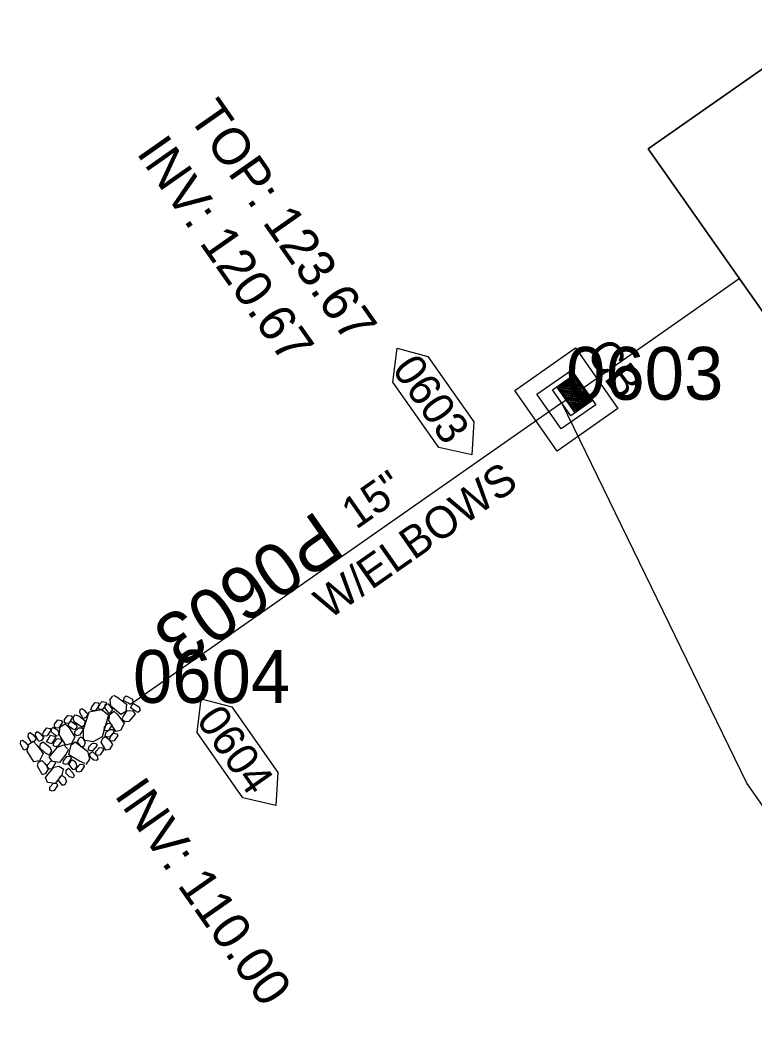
# Model space of a CAD drawing. Extents: x 2296558 to 2299313, y 599200 to 601383.
# Drawn here: x 2297890.7 to 2297960.1, y 600322.8 to 600419.2 of the extents above; entities that cross this region are included whole.
import ezdxf

# ---------------------------------------------------------------- set-up
doc = ezdxf.new("R2010")
doc.units = 0
for name, color, linetype in [('Prop Drainage Structure Box Number Symbol CELL', 7, 'Continuous'), ('Prop Drainage Structure Catch Basin Grate 840 03G CELL', 7, 'Continuous'), ('Prop Drainage Structure Catch Basin Grate 840 03G Label', 7, 'Continuous'), ('Prop Drainage Structure Pipe Alternate 15in', 7, 'Continuous'), ('Prop Drainage Structure Pipe Alternate 15in Label', 7, 'Continuous'), ('Prop Drainage Structure Plot Symbol 20 Scale', 7, 'Continuous'), ('Prop Drainage Structure Plot Symbol 50 Scale', 7, 'Continuous'), ('Prop Drainage Structure Tops and Inverts LABEL', 7, 'Continuous'), ('Prop Erosion Rip Rap Pad at Outlet CELL', 7, 'Continuous'), ('Prop Plan Preparation Watershed Post Construction', 7, 'Continuous'), ('Scratch_Level_3', 7, 'Continuous'), ('Scratch_Level_5', 7, 'Continuous')]:
    doc.layers.add(name, color=color, linetype=linetype)

msp = doc.modelspace()

# ---------------------------------------------------------------- linework, layer by layer
at = {"layer": 'Prop Drainage Structure Box Number Symbol CELL'}
for points in [[(2297929.189, 600387.346), (2297933.527, 600381.151), (2297933.35, 600378.022), (2297930.234, 600378.729), (2297925.895, 600384.924), (2297926.278, 600388.121), (2297929.189, 600387.346)], [(2297910.665, 600354.186), (2297915.004, 600347.992), (2297914.828, 600344.863), (2297911.711, 600345.569), (2297907.372, 600351.763), (2297907.754, 600354.96), (2297910.665, 600354.186)]]:
    msp.add_lwpolyline(points, dxfattribs=at)
at = {"layer": 'Prop Drainage Structure Catch Basin Grate 840 03G CELL'}
for p, q in [((2297942.139, 600384.807), (2297943.62, 600384.527)), ((2297942.231, 600385.046), (2297942.231, 600385.046)), ((2297943.434, 600384.636), (2297942.342, 600384.843)), ((2297942.365, 600384.966), (2297943.458, 600384.759)), ((2297943.272, 600384.868), (2297942.568, 600385.001)), ((2297942.591, 600385.124), (2297943.295, 600384.991)), ((2297943.109, 600385.1), (2297942.795, 600385.16)), ((2297942.818, 600385.283), (2297943.132, 600385.223)), ((2297943.597, 600384.404), (2297942.115, 600384.684)), ((2297943.114, 600383.847), (2297943.114, 600383.847)), ((2297943.392, 600383.966), (2297944.108, 600383.83)), ((2297943.618, 600384.124), (2297943.945, 600384.062)), ((2297943.89, 600384.391), (2297943.89, 600384.391)), ((2297941.851, 600382.963), (2297941.851, 600382.963)), ((2297942.502, 600383.328), (2297944.127, 600383.021)), ((2297942.664, 600383.096), (2297943.9, 600382.862)), ((2297942.713, 600383.49), (2297944.353, 600383.179)), ((2297942.939, 600383.648), (2297944.433, 600383.365)), ((2297943.165, 600383.807), (2297944.271, 600383.598)), ((2297942.827, 600382.864), (2297943.674, 600382.704)), ((2297942.989, 600382.632), (2297943.448, 600382.545)), ((2297943.198, 600382.264), (2297943.129, 600382.277)), ((2297943.152, 600382.4), (2297943.221, 600382.386)), ((2297943.974, 600382.618), (2297943.974, 600382.618))]:
    msp.add_line(p, q, dxfattribs=at)
for points in [[(2297943.121, 600382.021), (2297941.4, 600384.478), (2297943.038, 600385.625), (2297944.759, 600383.168), (2297942.711, 600381.734), (2297940.99, 600384.191), (2297941.4, 600384.478)], [(2297943.123, 600382.035), (2297941.414, 600384.476), (2297943.036, 600385.611), (2297944.745, 600383.171), (2297943.123, 600382.035)], [(2297943.005, 600385.437), (2297944.57, 600383.201), (2297943.154, 600382.209), (2297941.588, 600384.445), (2297943.005, 600385.437)], [(2297941.686, 600384.49), (2297943.447, 600384.157), (2297943.304, 600384.056), (2297941.663, 600384.367)], [(2297941.851, 600384.257), (2297943.22, 600383.998), (2297943.077, 600383.898), (2297941.828, 600384.134)], [(2297941.912, 600384.649), (2297943.673, 600384.315), (2297943.53, 600384.215), (2297941.889, 600384.526)], [(2297942.014, 600384.025), (2297942.994, 600383.839), (2297942.851, 600383.739), (2297941.991, 600383.902)], [(2297944.085, 600383.707), (2297943.249, 600383.865), (2297943.392, 600383.966)], [(2297943.922, 600383.939), (2297943.475, 600384.024), (2297943.618, 600384.124)], [(2297942.176, 600383.793), (2297942.768, 600383.681), (2297942.625, 600383.581), (2297942.153, 600383.67)], [(2297942.339, 600383.561), (2297942.541, 600383.522), (2297942.398, 600383.422), (2297942.316, 600383.438)], [(2297944.104, 600382.898), (2297942.478, 600383.206), (2297942.502, 600383.328)], [(2297944.33, 600383.056), (2297942.57, 600383.39), (2297942.713, 600383.49)], [(2297943.877, 600382.739), (2297942.641, 600382.973), (2297942.664, 600383.096)], [(2297944.41, 600383.243), (2297942.796, 600383.548), (2297942.939, 600383.648)], [(2297944.247, 600383.475), (2297943.022, 600383.707), (2297943.165, 600383.807)], [(2297943.651, 600382.581), (2297942.804, 600382.741), (2297942.827, 600382.864)], [(2297943.424, 600382.422), (2297942.966, 600382.509), (2297942.989, 600382.632)]]:
    msp.add_lwpolyline(points, dxfattribs=at)
for centre, start, end in [((2297942.127, 600384.746), 79.2754, 259.2754), ((2297942.353, 600384.904), 79.2754, 259.2754), ((2297942.58, 600385.063), 79.2754, 259.2754), ((2297942.806, 600385.221), 79.2754, 259.2754), ((2297943.121, 600385.162), 259.2754, 79.2754), ((2297943.283, 600384.93), 259.2754, 79.2754), ((2297941.674, 600384.429), 79.2754, 259.2754), ((2297941.84, 600384.196), 79.2754, 259.2754), ((2297941.901, 600384.587), 79.2754, 259.2754), ((2297942.002, 600383.964), 79.2754, 259.2754), ((2297943.446, 600384.697), 259.2754, 79.2754), ((2297943.609, 600384.465), 259.2754, 79.2754), ((2297943.934, 600384.001), 259.2754, 79.2754), ((2297942.165, 600383.731), 79.2754, 259.2754), ((2297942.327, 600383.499), 79.2754, 259.2754), ((2297944.096, 600383.768), 259.2754, 79.2754), ((2297944.115, 600382.959), 259.2754, 79.2754), ((2297944.259, 600383.536), 259.2754, 79.2754), ((2297944.342, 600383.118), 259.2754, 79.2754), ((2297944.422, 600383.304), 259.2754, 79.2754), ((2297943.14, 600382.338), 79.2754, 259.2754), ((2297943.21, 600382.325), 259.2754, 79.2754), ((2297943.436, 600382.484), 259.2754, 79.2754), ((2297943.662, 600382.642), 259.2754, 79.2754), ((2297943.889, 600382.801), 259.2754, 79.2754)]:
    msp.add_arc(centre, 0.0625, start, end, dxfattribs=at)
at = {"layer": 'Prop Drainage Structure Pipe Alternate 15in'}
msp.add_line((2297941.851, 600382.963), (2297901.304, 600354.569), dxfattribs=at)
at = {"layer": 'Prop Drainage Structure Plot Symbol 20 Scale'}
msp.add_lwpolyline([(2297942.785, 600386.059), (2297945.08, 600382.782), (2297941.803, 600380.488), (2297939.509, 600383.764)], close=True, dxfattribs=at)
at = {"layer": 'Prop Drainage Structure Plot Symbol 50 Scale'}
msp.add_lwpolyline([(2297943.154, 600388.148), (2297947.169, 600382.414), (2297941.435, 600378.399), (2297937.42, 600384.133)], close=True, dxfattribs=at)
at = {"layer": 'Prop Erosion Rip Rap Pad at Outlet CELL'}
msp.add_line((2297901.304, 600354.569), (2297901.304, 600354.569), dxfattribs=at)
msp.add_line((2297901.304, 600354.569), (2297901.304, 600354.569), dxfattribs=at)
for points in [[(2297899.5, 600355.292), (2297899.883, 600355.072), (2297900.709, 600354.459), (2297900.628, 600353.747), (2297900.166, 600353.469), (2297899.229, 600354.263), (2297899.135, 600354.898), (2297899.398, 600355.22)], [(2297901.057, 600354.398), (2297900.874, 600354.529), (2297900.399, 600354.792), (2297900.52, 600355.121), (2297900.674, 600355.228), (2297901.254, 600354.902), (2297901.303, 600354.57), (2297901.057, 600354.398)], [(2297896.488, 600354.037), (2297896.732, 600353.841), (2297897.052, 600353.471), (2297896.84, 600353.185), (2297896.589, 600353.085), (2297896.275, 600353.643), (2297896.32, 600353.95), (2297896.488, 600354.037)], [(2297897.337, 600353.914), (2297897.406, 600354.207), (2297897.734, 600354.589), (2297898.026, 600354.564), (2297898.155, 600354.38), (2297897.758, 600353.858), (2297897.536, 600353.825), (2297897.337, 600353.914)], [(2297898.048, 600354.031), (2297898.063, 600354.316), (2297898.39, 600354.698), (2297898.704, 600354.642), (2297898.811, 600354.489), (2297898.459, 600353.967), (2297898.217, 600353.92), (2297898.048, 600354.031)], [(2297898.964, 600354.489), (2297899.103, 600354.312), (2297899.372, 600353.95), (2297899.197, 600353.676), (2297899.044, 600353.568), (2297898.689, 600354.053), (2297898.691, 600354.42), (2297898.964, 600354.489)], [(2297901.761, 600353.655), (2297901.56, 600353.789), (2297901.064, 600354.083), (2297901.224, 600354.378), (2297901.37, 600354.495), (2297901.898, 600354.178), (2297901.999, 600353.837), (2297901.761, 600353.655)], [(2297894.819, 600352.715), (2297894.833, 600353), (2297895.161, 600353.382), (2297895.474, 600353.327), (2297895.582, 600353.173), (2297895.237, 600352.642), (2297894.988, 600352.605), (2297894.819, 600352.715)], [(2297895.853, 600353.44), (2297896.202, 600353.333), (2297896.763, 600352.902), (2297896.711, 600352.454), (2297896.466, 600352.282), (2297895.733, 600352.761), (2297895.665, 600353.186), (2297895.853, 600353.44)], [(2297896.643, 600351.2), (2297896.623, 600352.056), (2297897.158, 600353.712), (2297898.345, 600353.934), (2297899.002, 600353.432), (2297898.394, 600351.358), (2297897.538, 600350.881), (2297896.605, 600351.036)], [(2297899.501, 600353.766), (2297899.883, 600353.438), (2297900.484, 600352.623), (2297900.139, 600351.939), (2297899.693, 600351.856), (2297899.025, 600352.898), (2297899.126, 600353.473), (2297899.501, 600353.766)], [(2297900.261, 600352.986), (2297900.399, 600353.311), (2297900.744, 600353.843), (2297901.285, 600353.81), (2297901.525, 600353.49), (2297900.91, 600352.8), (2297900.557, 600352.781), (2297900.261, 600352.986)], [(2297892.745, 600351.492), (2297892.846, 600351.807), (2297893.159, 600352.209), (2297893.442, 600352.132), (2297893.542, 600351.989), (2297893.194, 600351.44), (2297892.945, 600351.403), (2297892.745, 600351.492)], [(2297894.135, 600351.382), (2297893.952, 600351.513), (2297893.58, 600351.848), (2297893.625, 600352.154), (2297893.741, 600352.25), (2297894.215, 600351.987), (2297894.295, 600351.677), (2297894.206, 600351.477)], [(2297893.872, 600352.281), (2297893.886, 600352.566), (2297894.214, 600352.948), (2297894.527, 600352.893), (2297894.635, 600352.739), (2297894.29, 600352.207), (2297894.041, 600352.17), (2297893.872, 600352.281)], [(2297894.892, 600352.568), (2297895.285, 600352.202), (2297895.804, 600351.33), (2297895.492, 600350.73), (2297894.969, 600350.562), (2297894.342, 600351.588), (2297894.433, 600352.308), (2297894.892, 600352.568)], [(2297895.816, 600352.01), (2297895.602, 600352.12), (2297895.149, 600352.397), (2297895.3, 600352.747), (2297895.433, 600352.84), (2297895.972, 600352.485), (2297895.998, 600352.274), (2297895.816, 600352.01)], [(2297895.82, 600351.57), (2297895.824, 600351.847), (2297896.183, 600352.206), (2297896.468, 600352.191), (2297896.597, 600352.007), (2297896.237, 600351.496), (2297895.989, 600351.459), (2297895.82, 600351.57)], [(2297898.587, 600351.997), (2297898.602, 600352.282), (2297898.937, 600352.654), (2297899.246, 600352.626), (2297899.323, 600352.451), (2297898.984, 600351.954), (2297898.787, 600351.908), (2297898.587, 600351.997)], [(2297898.691, 600351.414), (2297898.746, 600351.727), (2297899.092, 600352.061), (2297899.387, 600352.054), (2297899.516, 600351.869), (2297899.109, 600351.34), (2297898.891, 600351.325), (2297898.691, 600351.414)], [(2297891.598, 600351.757), (2297891.842, 600351.562), (2297892.163, 600351.191), (2297891.951, 600350.905), (2297891.7, 600350.806), (2297891.386, 600351.364), (2297891.431, 600351.67), (2297891.598, 600351.757)], [(2297892.279, 600351.853), (2297892.533, 600351.664), (2297892.854, 600351.294), (2297892.642, 600351.008), (2297892.391, 600350.909), (2297892.077, 600351.467), (2297892.122, 600351.773), (2297892.279, 600351.853)], [(2297893.134, 600350.894), (2297893.244, 600351.063), (2297893.522, 600351.517), (2297893.888, 600351.408), (2297893.996, 600351.254), (2297893.61, 600350.694), (2297893.355, 600350.775), (2297893.134, 600350.894)], [(2297893.801, 600350.507), (2297893.839, 600350.824), (2297894.174, 600351.196), (2297894.487, 600351.14), (2297894.574, 600350.972), (2297894.228, 600350.486), (2297894.001, 600350.418), (2297893.801, 600350.507)], [(2297896.373, 600351.347), (2297896.647, 600351.173), (2297896.802, 600350.777), (2297896.64, 600350.42), (2297896.422, 600350.404), (2297896.068, 600350.889), (2297896.219, 600351.239), (2297896.373, 600351.347)], [(2297898.685, 600351.379), (2297899.017, 600351.123), (2297899.371, 600350.639), (2297899.088, 600350.15), (2297898.746, 600350.094), (2297898.312, 600350.843), (2297898.449, 600351.214), (2297898.685, 600351.379)], [(2297899.133, 600351.021), (2297899.141, 600351.316), (2297899.475, 600351.688), (2297899.792, 600351.65), (2297899.869, 600351.475), (2297899.523, 600350.989), (2297899.333, 600350.932), (2297899.133, 600351.021)], [(2297890.873, 600351.051), (2297891.116, 600350.855), (2297891.437, 600350.484), (2297891.225, 600350.199), (2297890.974, 600350.099), (2297890.66, 600350.657), (2297890.705, 600350.964), (2297890.873, 600351.051)], [(2297891.857, 600350.931), (2297892.222, 600350.561), (2297892.823, 600349.791), (2297892.457, 600349.093), (2297891.936, 600348.987), (2297891.288, 600349.999), (2297891.434, 600350.62), (2297891.857, 600350.931)], [(2297893.367, 600349.624), (2297893.02, 600349.792), (2297892.499, 600350.297), (2297892.572, 600350.715), (2297892.818, 600350.887), (2297893.479, 600350.358), (2297893.612, 600349.993), (2297893.367, 600349.624)], [(2297895.218, 600350.141), (2297894.998, 600349.758), (2297894.355, 600348.911), (2297893.683, 600349.02), (2297893.371, 600349.443), (2297894.179, 600350.36), (2297894.76, 600350.599), (2297895.122, 600350.212)], [(2297896.753, 600348.82), (2297896.262, 600349.041), (2297895.25, 600349.66), (2297895.45, 600350.594), (2297895.842, 600350.884), (2297897.021, 600349.985), (2297897.204, 600349.243), (2297896.835, 600348.725)], [(2297897.101, 600350.132), (2297897.14, 600350.404), (2297897.479, 600350.748), (2297897.781, 600350.73), (2297897.91, 600350.546), (2297897.519, 600350.059), (2297897.301, 600350.043), (2297897.101, 600350.132)], [(2297897.784, 600349.68), (2297897.809, 600349.972), (2297898.143, 600350.343), (2297898.442, 600350.309), (2297898.519, 600350.133), (2297898.191, 600349.644), (2297897.994, 600349.598), (2297897.784, 600349.68)], [(2297894.71, 600348.839), (2297894.736, 600349.086), (2297895.075, 600349.538), (2297895.389, 600349.483), (2297895.466, 600349.308), (2297895.121, 600348.776), (2297894.931, 600348.72), (2297894.71, 600348.839)], [(2297895.579, 600349.189), (2297895.854, 600349.015), (2297896.009, 600348.619), (2297895.847, 600348.262), (2297895.629, 600348.247), (2297895.274, 600348.731), (2297895.426, 600349.081), (2297895.579, 600349.189)], [(2297897.853, 600349.102), (2297897.592, 600349.148), (2297897.253, 600349.414), (2297897.234, 600349.768), (2297897.493, 600349.964), (2297897.909, 600349.523), (2297897.999, 600349.22), (2297897.853, 600349.102)], [(2297892.685, 600349.116), (2297892.955, 600348.862), (2297893.331, 600348.347), (2297893.023, 600347.871), (2297892.744, 600347.768), (2297892.278, 600348.586), (2297892.387, 600348.953), (2297892.685, 600349.116)], [(2297894.713, 600348.247), (2297894.565, 600347.761), (2297893.953, 600346.936), (2297893.24, 600347.016), (2297893.031, 600347.511), (2297893.81, 600348.469), (2297894.286, 600348.573), (2297894.775, 600348.29)], [(2297893.215, 600348.403), (2297893.24, 600348.695), (2297893.56, 600349.087), (2297893.873, 600349.032), (2297893.981, 600348.878), (2297893.626, 600348.339), (2297893.384, 600348.292), (2297893.215, 600348.403)], [(2297895.646, 600347.481), (2297895.311, 600347.567), (2297894.989, 600347.875), (2297894.974, 600348.2), (2297895.213, 600348.383), (2297895.629, 600347.942), (2297895.75, 600347.66), (2297895.646, 600347.481)], [(2297895.969, 600348.088), (2297895.976, 600348.383), (2297896.311, 600348.755), (2297896.62, 600348.727), (2297896.697, 600348.552), (2297896.368, 600348.062), (2297896.179, 600348.006), (2297895.969, 600348.088)], [(2297894.59, 600347.703), (2297894.855, 600347.522), (2297895.009, 600347.126), (2297894.84, 600346.779), (2297894.622, 600346.764), (2297894.268, 600347.248), (2297894.437, 600347.595), (2297894.59, 600347.703)], [(2297893.447, 600346.307), (2297893.454, 600346.602), (2297893.789, 600346.973), (2297894.105, 600346.936), (2297894.182, 600346.761), (2297893.853, 600346.271), (2297893.657, 600346.225), (2297893.447, 600346.307)]]:
    msp.add_lwpolyline(points, dxfattribs=at)
at = {"layer": 'Prop Plan Preparation Watershed Post Construction'}
for p, q in [((2297950.039, 600407.009), (2297967.377, 600419.15)), ((2298066.924, 600240.095), (2297950.039, 600407.009)), ((2297941.851, 600382.963), (2297958.643, 600394.722))]:
    msp.add_line(p, q, dxfattribs=at)
msp.add_lwpolyline([(2297958.643, 600394.722), (2298066.924, 600240.095), (2298044.979, 600224.727), (2297959.371, 600346.975), (2297941.851, 600382.963)], dxfattribs=at)
at = {"layer": 'Scratch_Level_5'}
for p, q in [((2297967.377, 600419.15), (2297950.039, 600407.009)), ((2297950.039, 600407.009), (2297952.496, 600408.729)), ((2297950.039, 600407.009), (2298066.924, 600240.095))]:
    msp.add_line(p, q, dxfattribs=at)

# ---------------------------------------------------------------- texts
at = {"layer": 'Prop Drainage Structure Box Number Symbol CELL'}
for s, rotation, p in [('0603', 305.0012, (2297925.727, 600386.127)), ('0604', 305.01181, (2297907.213, 600352.953))]:
    msp.add_text(s, height=3, rotation=rotation, dxfattribs=at).set_placement(p)
at = {"layer": 'Prop Drainage Structure Catch Basin Grate 840 03G Label'}
msp.add_text('CB', height=3, rotation=306.15956, dxfattribs=at).set_placement((2297944.065, 600387.618))
at = {"layer": 'Prop Drainage Structure Pipe Alternate 15in Label'}
for s, p in [('W/ELBOWS', (2297919.827, 600362.397)), ('15"', (2297922.407, 600370.918))]:
    msp.add_text(s, height=3, rotation=35.00272, dxfattribs=at).set_placement(p)
at = {"layer": 'Prop Drainage Structure Tops and Inverts LABEL'}
for s, p in [('TOP: 123.67', (2297906.475, 600410.052)), ('INV: 120.67', (2297901.56, 600406.611)), ('INV: 110.00', (2297899.47, 600345.835))]:
    msp.add_text(s, height=3.5, rotation=305.00278, dxfattribs=at).set_placement(p)
at = {"layer": 'Scratch_Level_3'}
msp.add_text('P0603', height=5, rotation=215.00272, dxfattribs=at).set_placement((2297918.709, 600372.861))
at = {"layer": 'Scratch_Level_5'}
for s, p in [('0603', (2297942.26, 600383.249)), ('0604', (2297901.304, 600354.569))]:
    msp.add_text(s, height=5, dxfattribs=at).set_placement(p)

doc.saveas('drawing.dxf')
